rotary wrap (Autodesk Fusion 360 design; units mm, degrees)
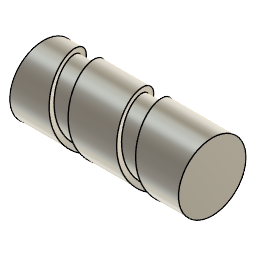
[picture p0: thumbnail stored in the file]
sketch "Sketch1" plane through (0, 0, 0) normal (0, 1, 0) x axis (1, 0, 0)
  line L1 (127, 0) -> (0, 0)
  line L2 (127, -25.4) -> (127, 0)
  line L3 (0, -25.4) -> (127, -25.4)
  line L4 (0, 0) -> (0, -25.4)
  point P1 (0, 0)
  point P2 (0, 0)
  point P6 (0, 0)
  point P3 (127, 0)
  coincident P1 P2
  horizontal L1
  perpendicular L1 L2
  perpendicular L2 L3
  coincident P1 P6
  perpendicular L1 L4
  dimension "d1" = 50.8
  dimension "d2" distance P2 P3 = 127
revolve "Revolve1" sketch "Sketch1" AlongAngle 360
coil_primitive "CoilPrimitive1" Diameter 57.15 SectionSize 14.2875 TaperAngle 0 Height -101.6
move "Move1"
combine "Combine1"
fillet "Fillet1" radius 4.445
